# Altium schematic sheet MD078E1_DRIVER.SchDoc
size 431 x 279 mm; Date: Not shown in title block; ApprovedBy: Not shown in title block; CheckedBy: Not shown in title block; Author: Not shown in title block; CompanyName: Not shown in title block; Engineer: Not shown in title block; Organization: Not shown in title block; Address1: Not shown in title block; Address2: Not shown in title block; Address3: Not shown in title block; Address4: Not shown in title block; DocumentNumber: 2; Revision: Use project parameter SCH_Rev; SheetNumber: 3; SheetTotal: 5; PageSetup: Record=PageOptions¦CenterHorizontal=True¦CenterVertical=True¦PrintScale=1.00¦XCorrection=1.00¦YCorrection=1.00¦PrintKind=0¦BorderSize=5000000¦LeftOffset=0¦BottomOffset=0¦Orientation=2¦PaperLength=1000¦PaperWidth=1000¦Scale=100¦PaperSource=15¦PrintQuality=600¦MediaType=1¦DitherType=10¦PaperKind=Letter¦PrintScaleMode=1
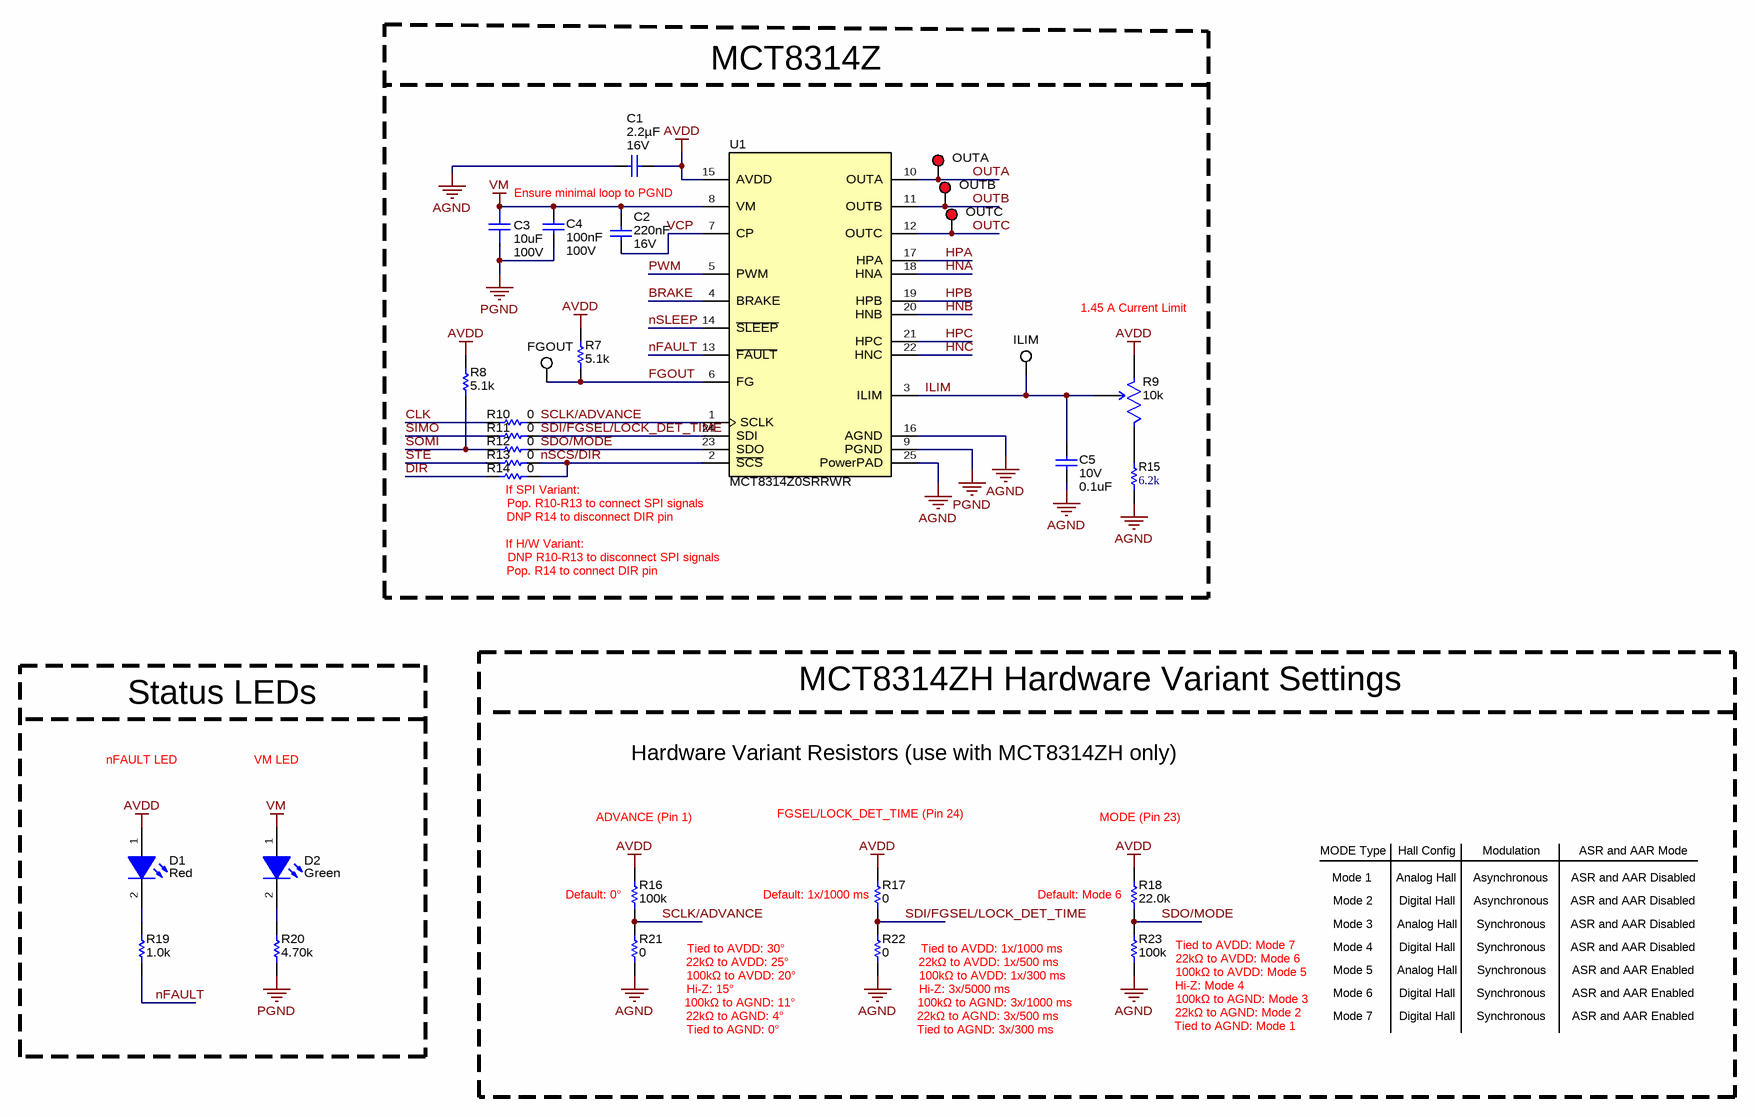
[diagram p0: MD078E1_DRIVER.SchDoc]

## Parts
C1  VDC_V: 16V  Cap_F: 2.2µF  [0603L]  (hidden comment: GRM188Z71C225KE43)
C2  Cap_F: 220nF  VDC_V: 16V  [0603]  (hidden comment: C0603C224K4RACTU)
C3  ValueDisplayed: 10uF  VDC_V: 100V  [FP-C3216X6S2A106K160AC_1206-MFG]  (hidden comment: C3216X6S2A106K160AC)
C4  Cap_F: 100nF  VDC_V: 100V  [0603]  (hidden comment: GCJ188R72A104KA01D)
C5  VDC_V: 10V  ValueDisplayed: 0.1uF  [0402]  (hidden comment: C1005X5R1A104K050BA)
D1  value Red  [LED_LTST-C170_Red]  (hidden comment: LTST-C170KRKT)
D2  value Green  [LTST-C170KGKT_Green]  (hidden comment: LTST-C170KGKT)
R7  ValueDisplayed: 5.1k  [0603L]  (hidden comment: RC0603JR-075K1L)
R8  ValueDisplayed: 5.1k  [0603L]  (hidden comment: RC0603JR-075K1L)
R9  value 10k  [Bourns_3352T]  (hidden comment: 3352T-1-103LF)
R10  ValueDisplayed: 0  [0603L]  (hidden comment: ERJ-3GEY0R00V)
R11  ValueDisplayed: 0  [0603L]  (hidden comment: ERJ-3GEY0R00V)
R12  ValueDisplayed: 0  [0603L]  (hidden comment: ERJ-3GEY0R00V)
R13  ValueDisplayed: 0  [0603L]  (hidden comment: ERJ-3GEY0R00V)
R14  ValueDisplayed: 0  [0603L]  (hidden comment: ERJ-3GEY0R00V)
R15  ValueDisplayed: 6.2k  [0603]  (hidden comment: RC0603JR-076K2L)
R16  ValueDisplayed: 100k  [0603L]  (hidden comment: ERA-3AEB104V)
R17  ValueDisplayed: 0  [0603L]  (hidden comment: ERJ-3GEY0R00V)
R18  ValueDisplayed: 22.0k  [0603L]  (hidden comment: ERJ-3EKF2202V)
R19  ValueDisplayed: 1.0k  [0603L]  (hidden comment: RC0603JR-071KL)
R20  ValueDisplayed: 4.70k  [0603L]  (hidden comment: RT0603BRD074K7L)
R21  ValueDisplayed: 0  [0603L]  (hidden comment: ERJ-3GEY0R00V)
R22  ValueDisplayed: 0  [0603L]  (hidden comment: ERJ-3GEY0R00V)
R23  ValueDisplayed: 100k  [0603L]  (hidden comment: ERA-3AEB104V)
TP5  OUTA  [Keystone5000]
TP6  OUTB  [Keystone5000]
TP7  OUTC  [Keystone5000]
TP8  ILIM  [Keystone5002]
TP9  FGOUT  [Keystone5002]
U1  MCT8314Z0SRRWR  [RRW0024A-MFG]

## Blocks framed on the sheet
MCT8314Z: C1-C5 R7-R15 TP5-TP9 U1
MCT8314ZH Hardware Variant Settings: R16-R18 R21-R23
Status LEDs: D1 D2 R19 R20

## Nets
AGND: C1.2 C5.2 R15.1 R21.1 R22.1 R23.1 U1.16(AGND) U1.25(PowerPAD)
AVDD: C1.1 D1.1(A) R7.2 R8.2 R9.3(CW) R16.2 R17.2 R18.2 U1.15(AVDD)
PGND: C3.1 C4.2 R20.1 U1.9(PGND)
VM: C2.1 C3.2 C4.1 D2.1(A) U1.8(VM)
BRAKE: U1.4(BRAKE)
CLK: R10.1
DIR: R14.1
FGOUT: R7.1 TP9.1 U1.6(FG)
HNA: U1.18(HNA)
HNB: U1.20(HNB)
HNC: U1.22(HNC)
HPA: U1.17(HPA)
HPB: U1.19(HPB)
HPC: U1.21(HPC)
ILIM: C5.1 R9.2(WIPER) TP8.1 U1.3(ILIM)
nFAULT: R19.1 U1.13(~{FAULT})
nSCS/DIR: R13.2 R14.2 U1.2(~{SCS})
nSLEEP: U1.14(~{SLEEP})
OUTA: TP5.1 U1.10(OUTA)
OUTB: TP6.1 U1.11(OUTB)
OUTC: TP7.1 U1.12(OUTC)
PWM: U1.5(PWM)
SCLK/ADVANCE: R10.2 R16.1 R21.2 U1.1(SCLK)
SDI/FGSEL/LOCK_DET_TIME: R11.2 R17.1 R22.2 U1.24(SDI)
SDO/MODE: R12.2 R18.1 R23.2 U1.23(SDO)
SIMO: R11.1
SOMI: R8.1 R12.1
STE: R13.1
VCP: C2.2 U1.7(CP)
NetD1_2: D1.2(K) R19.2
NetD2_2: D2.2(K) R20.2
NetR9_1: R9.1(CCW) R15.2

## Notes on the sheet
- Ensure minimal loop to PGND
- 1.45 A Current Limit
- (near R14) If SPI Variant:
- DNP R14 to disconnect DIR pin
- Pop. R10-R13 to connect SPI signals
- If H/W Variant:
- Pop. R14 to connect DIR pin
- DNP R10-R13 to disconnect SPI signals
- nFAULT LED
- VM LED
- Hardware Variant Resistors (use with MCT8314ZH only)
- ADVANCE (Pin 1)
- FGSEL/LOCK_DET_TIME (Pin 24)
- MODE (Pin 23)
- MODE Type
- Hall Config
- Modulation
- ASR and AAR Mode
- (near R16) Default: 0°
- (near R17) Default: 1x/1000 ms
- (near R18) Default: Mode 6
- Mode 1
- Mode 2
- Mode 3
- Analog Hall
- Digital Hall
- Asynchronous
- Synchronous
- ASR and AAR Disabled
- (near R21) Hi-Z: 15°
- Tied to AVDD: 30°
- 22kΩ to AVDD: 25°
- 100kΩ to AVDD: 20°
- (near R22) Hi-Z: 3x/5000 ms
- Tied to AVDD: 1x/1000 ms
- 22kΩ to AVDD: 1x/500 ms
- 100kΩ to AVDD: 1x/300 ms
- (near R23) Hi-Z: Mode 4
- Tied to AVDD: Mode 7
- 22kΩ to AVDD: Mode 6
- (near R23) 100kΩ to AVDD: Mode 5
- Mode 4
- Mode 6
- Mode 5
- ASR and AAR Enabled
- Tied to AGND: 0°
- 22kΩ to AGND: 4°
- 100kΩ to AGND: 11°
- Tied to AGND: 3x/300 ms
- 22kΩ to AGND: 3x/500 ms
- 100kΩ to AGND: 3x/1000 ms
- Tied to AGND: Mode 1
- 22kΩ to AGND: Mode 2
- 100kΩ to AGND: Mode 3
- Mode 7

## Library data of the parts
C1 = CMP-0007499-4: CAP, CERM, 2.2 uF, 16 V, +/- 10%, X7R, 0603; Manufacturer: MuRata; TaMin_C: -55°C; Polarized: N; SizeAreaWB_mm2: 4.68; Value1: Unknown; U/M: EA; Value: 2.2uF; TaMax_C: 125°C; SizeZ_mm: 1; SizeX_mm: 1.6; SizeY_mm: 0.8; Cap_Case: 0603; SizeArea_mm2: 1.28; AEC Category: Q200
C2 = CMP-0006903-4: CAP, CERM, 0.22 uF, 16 V, +/- 10%, X7R, 0603; Manufacturer: Kemet; TaMin_C: -55°C; Polarized: N; SizeAreaWB_mm2: 4.68; Value1: Unknown; U/M: EA; Value: 0.22uF; TaMax_C: 125°C; SizeZ_mm: 1; SizeX_mm: 1.6; SizeY_mm: 0.8; SizeArea_mm2: 1.28; AEC Category: Q200
C3 = CMP-0098402-1: 10 µF ±10% 100V Ceramic Capacitor X6S 1206 (3216 Metric); Manufacturer: TDK; AEC Qualified: No; Cap_F: 10µF; SizeZ_mm: 1.9mm; TempCo: 22%; Value: 10µF
C4 = CMP-0064935-4: CAP, CERM, 0.1 uF, 100 V,+/- 10%, X7R, AEC-Q200 Grade 1, 0603; Manufacturer: MuRata; TaMin_C: -55°C; Polarized: N; SizeAreaWB_mm2: 4.68; Value1: Unknown; U/M: EA; Value: 0.1uF; TaMax_C: 125°C; SizeZ_mm: 1; SizeX_mm: 1.6; SizeY_mm: 0.8; SizeArea_mm2: 1.28; AEC Qualified: Y; AEC Category: Q200
C5 = CMP-0006259-2: CAP, CERM, 0.1 uF, 10 V, +/- 10%, X5R, 0402; Manufacturer: TDK; TaMin_C: -55°C; Polarized: N; SizeAreaWB_mm2: 3; Value1: Unknown; U/M: EA; Value: 0.1uF; TaMax_C: 85°C; SizeZ_mm: 0.6; SizeX_mm: 1; SizeY_mm: 0.5; Cap_F: 100nF; AEC Category: Q200
D1 = CMP-0002829-3: LED, Red, SMD; Manufacturer: Lite-On; Io_A: 20mA; SizeAreaWB_mm2: 6.75; Value1: W; SizeZ_mm: 1.2; SizeX_mm: 2; SizeY_mm: 1.25; Vf_V: 2V; SizeArea_mm2: 2.5; Type: AlInGaP
D2 = CMP-0002888-2: LED, Green, SMD; Manufacturer: Lite-On; Io_A: 20mA; Value1: W; Vf_V: 2V; Type: AlInGaP
R7 R8 = CMP-0025932-5: RES, 5.1 k, 5%, 0.1 W, 0603; Manufacturer: Yageo; Power_W: 100mW; TempCo: 100 ppm/C; Value_Code: 5k10; Value: 5.1k; EIA_Code: E24; SizeX_mm: 1.6; SizeY_mm: 0.8; SizeZ_mm: 1; Value2: 0.1W; SizeArea_mm2: 1.28; AEC Qualified: N; VDC_V: 75V; AEC Category: Q200; SizeAreaWB_mm2: 4.68
R9 = CMP-0093882-3: 10 kOhms 0.5W, 1/2W Through Hole Thumbwheel Potentiometer Top Adjustment; Manufacturer: Bourns; Voltage: 250V; TempCo: 100ppm/°C; Standoff Height: 0.64mm; Res_ohm: 10kΩ; Tolerance_%: 20%; Power: 500mW; AEC Qualified: No; SizeZ_mm: 4.32mm
R10-R14 R17 R21 R22 = CMP-0025874-4: RES, 0, 5%, 0.1 W, AEC-Q200 Grade 0, 0603; Manufacturer: Panasonic; Power_W: 100mW; TempCo: 600 ppm/C; Value_Code: 0000; Value: 0; EIA_Code: E24; SizeX_mm: 1.6; SizeY_mm: 0.8; SizeZ_mm: 1; Value2: 0.1W; SizeArea_mm2: 1.28; AEC Qualified: Y; VDC_V: 50V; AEC Category: Q200; SizeAreaWB_mm2: 4.68
R15 = CMP-0025937-5: RES, 6.2 k, 5%, 0.1 W, 0603; Manufacturer: Yageo; Power_W: 100mW; TempCo: 100 ppm/C; Value_Code: 6k20; Value: 6.2k; EIA_Code: E24; SizeX_mm: 1.6; SizeY_mm: 0.8; SizeZ_mm: 1; Value2: 0.1W; SizeArea_mm2: 1.28; AEC Qualified: N; VDC_V: 75V; AEC Category: Q200; SizeAreaWB_mm2: 4.68
R16 R23 = CMP-0023363-3: RES, 100 k, 0.1%, 0.1 W, AEC-Q200 Grade 0, 0603; Manufacturer: Panasonic; Power_W: 100mW; TempCo: 25 ppm/C; U/M: EA; Value: 100k; EIA_Code: E192; SizeX_mm: 1.6; SizeY_mm: 0.8; SizeZ_mm: 1; Value2: 0.1W; SizeArea_mm2: 1.28; AEC Qualified: Y; VDC_V: 75V; AEC Grade: 0; AEC Category: Q200
R18 = CMP-0022692-3: RES, 22.0 k, 1%, 0.1 W, AEC-Q200 Grade 0, 0603; Manufacturer: Panasonic; Power_W: 100mW; TempCo: 100 ppm/C; Value_Code: 22k0; U/M: EA; Value: 22.0k; Res_ohm: 22k; SizeX_mm: 1.6; SizeY_mm: 0.8; SizeZ_mm: 1; Value2: 0.1W; SizeArea_mm2: 1.28; AEC Qualified: Y; VDC_V: 50V; AEC Grade: 0; AEC Category: Q200
R19 = CMP-0025899-5: RES, 1.0 k, 5%, 0.1 W, 0603; Manufacturer: Yageo; Power_W: 100mW; TempCo: 100 ppm/C; Value_Code: 1k00; Value: 1.0k; EIA_Code: E24; Res_ohm: 1k; SizeX_mm: 1.6; SizeY_mm: 0.8; SizeZ_mm: 1; Value2: 0.1W; SizeArea_mm2: 1.28; AEC Qualified: N; VDC_V: 75V; AEC Category: Q200; SizeAreaWB_mm2: 4.68
R20 = CMP-0024300-2: RES, 4.70 k, 0.1%, 0.1 W, 0603; Manufacturer: Yageo America; Power_W: 100mW; TempCo: 25 ppm/C; Value_Code: 4k70; U/M: EA; Value: 4.70k; EIA_Code: E192; Res_ohm: 4.7k; SizeX_mm: 1.6; SizeY_mm: 0.8; SizeZ_mm: 1; Value2: 0.1W; SizeArea_mm2: 1.28; VDC_V: 75V; AEC Category: Q200
TP5-TP7 = CMP-0055137-2: Test Point, Miniature, Red, TH; Manufacturer: Keystone Electronics; ContactFinish: Silver; CNHeader: FALSE; CT: TRUE; Green_Lifecycle: Active; Green_REACh: Passed
TP8 TP9 = CMP-0055139-2: Test Point, Miniature, White, TH; Manufacturer: Keystone Electronics; CNHeader: FALSE; Green_Lifecycle: Active; Green_REACh: Passed; ContactFinish: Silver; CT: TRUE
U1 = CMP-0034379-1: Manufacturer: Texas Instruments; SizeZ_mm: 0.8mm; Standoff Height: 0mm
